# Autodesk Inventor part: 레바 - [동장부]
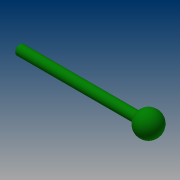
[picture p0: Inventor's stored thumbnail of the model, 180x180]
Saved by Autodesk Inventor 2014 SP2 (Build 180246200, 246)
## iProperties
Created: 2015-12
Part Number: 레바 - [동장부]
Material: 스테인리스강
Document SubType Name: Modeling
Designer: mduedu
Density: 8.08 g/cm^3
Mass: 30.7693 g
Surface Area: 20.8622 cm^2
Volume: 3.80808 cm^3
Appearance: 진녹색
Author: mduedu
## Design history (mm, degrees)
sketch "스케치1"
  geometry: C1 r 3 at (0, 0); 1 further point
  constraints: 1 centre point, 1 coincident
  dimensions: "d0" = 6 diameter of C1
extrude "돌출1" new body sketch "스케치1" distance "d1" = 80; taper "d2" = 0 deg
sketch "스케치2"
  geometry: L1 (7.5, 0)-(-6, 0); L2 (-6, 4.5)-(-6, 0); A1 r 7.5 centre (0, 0) between (7.5, 0) and (-6, 4.5); 2 further points
  constraints: 4 end point, 2 coincident, 2 point on circle, 1 centre point, 1 horizontal, 1 perpendicular, 1 point on line
  dimensions: "d3" = 15 diameter of A1; "d10" = 6 distance from line of L2 point (0, 0)
revolve "회전1" sketch "스케치2" stored, may be unused: angle "d4" = 90 deg
chamfer "모따기1" distance "d7" = 0.5; stored, may be unused: second distance "d8" = 2, angle "d9" = 45 deg
fillet "모깎기2" dims "d11" = 0.3
node "솔리드1"
